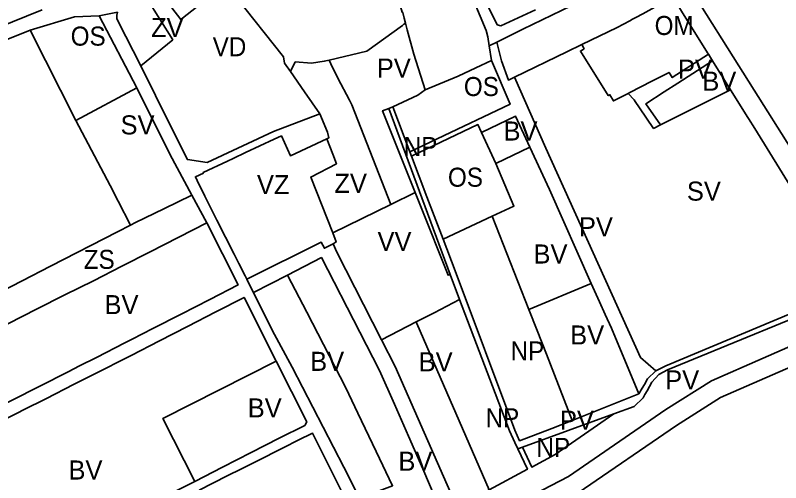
# Model space of a CAD drawing. Extents: x -650451 to -642268, y -1075216 to -1066610.
# Drawn here: x -648658 to -648056, y -1067753 to -1067385 of the extents above; entities that cross this region are included whole.
import ezdxf

# ---------------------------------------------------------------- set-up
doc = ezdxf.new("R2010")
doc.units = 0
doc.header["$LTSCALE"] = 6
doc.layers.add('1', color=7, linetype='Continuous', lineweight=35)
doc.layers.add('2', color=7, linetype='Continuous')
doc.layers.add('3', color=7, linetype='Continuous')

msp = doc.modelspace()

# ---------------------------------------------------------------- linework, layer by layer
at = {"layer": '1'}
for p, q in [((-648636.68, -1067380.92), (-648737.46, -1067421.52)), ((-648646.13, -1067396.91), (-648611.43, -1067386.42)), ((-648591.81, -1067385.65), (-648611.43, -1067386.42)), ((-648591.81, -1067385.65), (-648577.58, -1067382.79)), ((-648591.81, -1067385.65), (-648562.34, -1067442.47)), ((-648610.29, -1067468.28), (-648646.13, -1067396.91)), ((-648279.24, -1067406.38), (-648285.08, -1067409.24)), ((-648285.08, -1067409.24), (-648283.21, -1067420.88)), ((-648112.7, -1067416.03), (-648109.53, -1067421.13)), ((-648109.53, -1067421.13), (-648095.28, -1067444.06)), ((-648610.29, -1067468.28), (-648562.34, -1067442.47)), ((-648364.19, -1067458.619), (-648361, -1067457.36)), ((-648364.19, -1067458.619), (-648315.92, -1067589.37)), ((-648361, -1067457.36), (-648347.51, -1067492.87)), ((-648279.86, -1067502.11), (-648291.17, -1067477.57)), ((-648253.1, -1067489.23), (-648279.86, -1067502.11)), ((-648347.51, -1067492.87), (-648346.27, -1067496.14)), ((-648507.31, -1067548.84), (-648518.97, -1067527)), ((-648470.47, -1067603.64), (-648443.83, -1067589.92)), ((-648308.43, -1067609.15), (-648315.92, -1067589.37)), ((-648254.04, -1067616.96), (-648204.88, -1067596.54)), ((-648369.949, -1067640.851), (-648342.697, -1067626.806)), ((-648219.86, -1067704.42), (-648167.48, -1067683.45)), ((-648187.139, -1067699.179), (-648258.96, -1067725.37)), ((-648258.96, -1067725.37), (-648262.63, -1067726.71))]:
    msp.add_line(p, q, dxfattribs=at)
for points in [[(-648351.06, -1067391.62), (-648352.13, -1067387.54), (-648353.2, -1067383.1), (-648353.64, -1067382.91), (-648358.81, -1067364.78), (-648360.31, -1067359.89), (-648363.4, -1067349.23), (-648367.33, -1067340.58), (-648370.98, -1067331.37), (-648373.81, -1067324.53), (-648378.17, -1067313.98), (-648381.36, -1067306.74)], [(-647969.29, -1067609.79), (-647994.8, -1067572.37), (-648010.57, -1067549.31), (-648017.77, -1067537.87), (-648020.26, -1067533.91), (-648035.38, -1067509.89), (-648047.65, -1067490.38), (-648076.68, -1067444.23), (-648135.26, -1067351.13), (-648141.82, -1067342.88)], [(-648279.24, -1067406.38), (-648258.57, -1067396.29), (-648228.27, -1067381.48), (-648178.86, -1067357.46), (-648170.82, -1067354.57), (-648154.39, -1067349.06)], [(-648540.13, -1067358.49), (-648535.43, -1067364.69), (-648541.89, -1067369.86), (-648527.67, -1067388.73), (-648522.64, -1067384.7), (-648501.85, -1067367.87), (-648493.65, -1067361.24)], [(-648493.65, -1067361.24), (-648485.5, -1067371.06), (-648484.51, -1067370.58), (-648447.04, -1067418.08), (-648446.16, -1067422.92), (-648441.48, -1067429.63)], [(-648285.08, -1067409.24), (-648286.2, -1067402.2), (-648287.57, -1067397.28), (-648301.77, -1067363.07)], [(-648554.52, -1067371.95), (-648533.99, -1067404.51), (-648559.21, -1067425.12)], [(-648248.74, -1067380.92), (-648275.98, -1067393.72), (-648278.83, -1067392.79), (-648288.48, -1067372.88)], [(-648140.65, -1067371.06), (-648144.8, -1067373.45), (-648164.35, -1067384.16), (-648169.73, -1067387.11), (-648169.81, -1067386.98), (-648172.45, -1067388.4), (-648174.63, -1067389.58), (-648184.44, -1067394.86), (-648212.32, -1067408.39)], [(-648112.7, -1067416.03), (-648113.46, -1067414.8), (-648133.9, -1067381.99), (-648136.27, -1067378.19), (-648140.65, -1067371.06)], [(-648559.21, -1067425.12), (-648576.92, -1067390.11), (-648577.91, -1067387.81), (-648578.07, -1067385.28), (-648577.58, -1067382.79)], [(-648410.92, -1067420.63), (-648381.48, -1067413.68), (-648353.35, -1067393.29), (-648352.16, -1067392.42), (-648351.06, -1067391.62)], [(-648335.38, -1067444.07), (-648344.41, -1067416.04), (-648349.67, -1067396.88), (-648351.06, -1067391.62)], [(-648646.13, -1067396.91), (-648711.76, -1067423.39), (-648728.95, -1067430.33)], [(-648265.197, -1067434.03), (-648270.02, -1067436.37), (-648275.41, -1067421.3), (-648279.24, -1067406.38)], [(-648212.32, -1067408.39), (-648224.19, -1067414.14), (-648265.197, -1067434.03)], [(-648212.32, -1067408.39), (-648211.08, -1067410.6), (-648210.48, -1067411.68), (-648213.34, -1067413.46), (-648191.46, -1067448.59), (-648190.23, -1067447.83), (-648187.44, -1067452.8), (-648175.94, -1067446.89)], [(-648175.94, -1067446.89), (-648174.64, -1067446.22), (-648157.23, -1067437.28), (-648143.66, -1067430.3), (-648141.17, -1067434.4), (-648112.7, -1067416.03)], [(-648441.48, -1067429.63), (-648437.75, -1067421.99), (-648425, -1067423.05), (-648414.84, -1067421.56), (-648410.92, -1067420.63)], [(-648410.92, -1067420.63), (-648409.61, -1067423.44), (-648404.29, -1067434.9), (-648394.92, -1067452.23), (-648393.17, -1067455.88), (-648362.585, -1067534.204)], [(-648347.51, -1067492.87), (-648326.09, -1067482.7), (-648268.67, -1067455.43), (-648283.21, -1067420.88)], [(-648283.21, -1067420.88), (-648295.66, -1067426.76), (-648309.57, -1067433.34), (-648335.38, -1067444.07)], [(-648150.46, -1067471.66), (-648161.9, -1067454.92), (-648147.52, -1067445.69), (-648136.84, -1067438.83), (-648109.53, -1067421.13)], [(-648418.3, -1067462.86), (-648454.7, -1067476.79), (-648507.05, -1067501.14), (-648522.55, -1067498.89), (-648536.01, -1067471.76), (-648559.21, -1067425.12)], [(-648441.48, -1067429.63), (-648430.4, -1067445.51), (-648418.3, -1067462.86)], [(-648153.98, -1067665.43), (-648166.173, -1067654.853), (-648240.51, -1067489.9), (-648265.197, -1067434.03)], [(-648562.34, -1067442.47), (-648536.22, -1067494.67), (-648518.97, -1067527)], [(-648361, -1067457.36), (-648341.15, -1067448.14), (-648335.38, -1067444.07)], [(-648150.46, -1067471.66), (-648155.85, -1067474.35), (-648166.97, -1067458.18), (-648170.38, -1067453.23), (-648171.21, -1067452.01), (-648175.94, -1067446.89)], [(-648095.28, -1067444.06), (-648133.56, -1067463.2), (-648150.46, -1067471.66)], [(-648000.63, -1067599.14), (-648031.77, -1067546.6), (-648045.04, -1067525.15), (-648076.32, -1067474.6), (-648081.31, -1067466.54), (-648081.69, -1067465.92), (-648095.28, -1067444.06)], [(-648343.409, -1067524.81), (-648369.01, -1067460.52), (-648364.19, -1067458.619)], [(-648418.3, -1067462.86), (-648412.46, -1067477.42), (-648411.25, -1067481.73), (-648412.89, -1067482.55)], [(-648291.17, -1067477.57), (-648264.34, -1067464.83), (-648253.1, -1067489.23)], [(-648610.29, -1067468.28), (-648583.36, -1067519.43), (-648577.06, -1067531.62), (-648567.3, -1067550.48)], [(-648291.17, -1067477.57), (-648291.172, -1067477.571), (-648294.04, -1067471.35), (-648346.27, -1067496.14)], [(-648412.89, -1067482.55), (-648441.55, -1067495.94), (-648448.62, -1067480.25), (-648454.26, -1067482.89), (-648476.7, -1067493.38), (-648486.55, -1067498), (-648490.99, -1067500.08), (-648510.14, -1067509.04), (-648509.9, -1067509.58), (-648516.27, -1067512.46), (-648514.87, -1067515.48), (-648508.92, -1067527.65), (-648503.82, -1067537.85), (-648499.38, -1067546.74), (-648485.8, -1067573.49), (-648482.12, -1067580.73), (-648477.08, -1067590.47), (-648475.78, -1067593.11)], [(-648412.89, -1067482.55), (-648408.24, -1067494.59), (-648405.27, -1067502.27), (-648425.5, -1067512.73), (-648408.26, -1067556.58)], [(-648204.88, -1067596.54), (-648237.81, -1067522.42), (-648253.1, -1067489.23)], [(-648346.27, -1067496.14), (-648334.09, -1067528.2), (-648321.361, -1067561.69)], [(-648282.863, -1067543.596), (-648265.757, -1067535.555), (-648279.86, -1067502.11)], [(-648343.409, -1067524.81), (-648362.585, -1067534.204), (-648408.26, -1067556.58)], [(-648408.26, -1067556.58), (-648362.585, -1067534.205), (-648343.409, -1067524.81)], [(-648315.92, -1067589.37), (-648317.43, -1067590), (-648339.16, -1067535.48), (-648343.409, -1067524.81)], [(-648518.97, -1067527), (-648541.08, -1067537.74), (-648563.37, -1067548.58), (-648567.3, -1067550.48)], [(-648507.31, -1067548.84), (-648551.91, -1067571.47), (-648574.23, -1067582.89), (-648596.43, -1067594.35), (-648618.83, -1067605.54), (-648641.16, -1067616.88), (-648663.31, -1067628.15), (-648685.55, -1067639.55), (-648707.73, -1067650.94), (-648720.1, -1067657.12)], [(-648708.26, -1067712.07), (-648683.06, -1067699.88), (-648666.59, -1067691.63), (-648660.83, -1067688.75), (-648638.59, -1067677.44), (-648616.23, -1067666.06), (-648607.28, -1067661.48), (-648594.06, -1067654.71), (-648571.81, -1067643.31), (-648566.04, -1067640.39), (-648549.61, -1067632.06), (-648527.31, -1067620.61), (-648504.95, -1067609.19), (-648482.69, -1067597.72), (-648507.31, -1067548.84)], [(-648254.04, -1067616.96), (-648282.863, -1067543.596), (-648321.361, -1067561.69)], [(-648725.8, -1067632.36), (-648718.9, -1067628.79), (-648696.71, -1067617.33), (-648674.49, -1067605.85), (-648669.32, -1067603.18), (-648652.5, -1067594.5), (-648630.2, -1067582.97), (-648577.53, -1067555.77), (-648567.3, -1067550.48)], [(-648408.002, -1067565.219), (-648405.41, -1067563.84), (-648408.26, -1067556.58)], [(-648408.002, -1067565.219), (-648414.73, -1067568.8), (-648417.19, -1067564.02), (-648475.78, -1067593.11)], [(-648369.949, -1067640.851), (-648405.054, -1067571.837), (-648408.002, -1067565.219)], [(-648321.361, -1067561.69), (-648311.95, -1067586.45), (-648265.08, -1067712.06), (-648261.25, -1067720.39), (-648235.78, -1067710.79), (-648219.86, -1067704.42)], [(-648367.811, -1067802.994), (-648321.623, -1067778.399), (-648326, -1067769), (-648337.32, -1067742.59), (-648348.55, -1067716.71), (-648359.6, -1067691.58), (-648371.34, -1067665.08), (-648386.91, -1067634.83), (-648417.12, -1067576.17), (-648443.83, -1067589.92)], [(-648443.83, -1067589.92), (-648428.7, -1067619.24), (-648397.98, -1067678.79), (-648388.506, -1067698.645), (-648373.99, -1067728.95), (-648361.08, -1067755.88), (-648387.04, -1067765.67)], [(-648475.78, -1067593.11), (-648473.34, -1067598.06), (-648470.57, -1067603.69), (-648470.47, -1067603.64)], [(-648204.88, -1067596.54), (-648198.39, -1067610.97), (-648193.8, -1067621), (-648189.03, -1067631.71), (-648167.48, -1067683.45)], [(-648470.47, -1067603.64), (-648455.98, -1067633.3), (-648440.25, -1067662.32), (-648399.58, -1067741.31), (-648387.04, -1067765.67)], [(-648153.98, -1067665.43), (-648146.21, -1067661.3), (-648023.96, -1067610.13), (-648000.63, -1067599.14)], [(-648452.72, -1067657.62), (-648477.94, -1067607.47), (-648500.14, -1067618.94), (-648522.4, -1067630.35), (-648544.55, -1067641.82), (-648566.86, -1067653.13), (-648574.67, -1067657.12), (-648589.17, -1067664.52), (-648611.49, -1067675.9), (-648633.79, -1067687.24), (-648651.39, -1067696.1), (-648655.83, -1067698.33), (-648678.44, -1067709.73), (-648692.17, -1067716.68), (-648706.08, -1067723.56)], [(-648308.43, -1067609.15), (-648328.54, -1067619.51), (-648342.697, -1067626.806)], [(-648262.63, -1067726.71), (-648264.949, -1067721.79), (-648269.27, -1067712.6), (-648308.43, -1067609.15)], [(-647997.681, -1067604.11), (-648144.83, -1067664.48), (-648151.6, -1067668.12), (-648157.2, -1067674.32), (-648161, -1067680.96), (-648162.69, -1067684), (-648164.09, -1067686.51), (-648171.21, -1067693.37), (-648187.139, -1067699.179)], [(-647988.334, -1067619.747), (-648110.36, -1067673.133), (-648146.127, -1067695.8), (-648222.872, -1067748.412), (-648256.499, -1067766.091)], [(-648219.86, -1067704.42), (-648240.19, -1067652.12), (-648247.53, -1067633.53), (-648254.04, -1067616.96)], [(-648342.697, -1067626.806), (-648342.023, -1067628.096), (-648285.254, -1067759.009)], [(-647980.561, -1067632.719), (-648103.298, -1067686.416), (-648137.869, -1067708.325), (-648215.115, -1067761.28), (-648232.676, -1067770.513), (-648061.329, -1068158.649), (-647982.969, -1068116.575), (-647971.35, -1068144.48), (-647929.45, -1068244.16)], [(-648285.254, -1067759.009), (-648310.511, -1067772.476), (-648359.213, -1067661.956), (-648369.949, -1067640.851)], [(-648452.72, -1067657.62), (-648475.01, -1067668.94), (-648541.86, -1067702.86), (-648516.73, -1067752.57)], [(-648516.73, -1067752.57), (-648494.84, -1067741.06), (-648472.5, -1067729.76), (-648450.23, -1067718.32), (-648430.17, -1067708.33), (-648428.67, -1067705.52), (-648452.72, -1067657.62)], [(-648167.48, -1067683.45), (-648164.79, -1067678.96), (-648163.11, -1067676.17), (-648160.68, -1067671.55), (-648153.98, -1067665.43)], [(-648258.96, -1067725.37), (-648251.711, -1067741.124), (-648233.264, -1067731.288), (-648187.139, -1067699.179)], [(-648611.61, -1067932.63), (-648547.09, -1067899.87), (-648530.81, -1067891.61), (-648508.22, -1067880.38), (-648486.09, -1067868.98), (-648441.47, -1067846.37), (-648419.44, -1067835.3), (-648397.04, -1067823.85), (-648374.84, -1067812.43), (-648399.64, -1067763.26), (-648424.14, -1067714.34), (-648435.34, -1067720.01), (-648446.58, -1067725.71), (-648468.97, -1067736.91), (-648480.06, -1067742.47), (-648491.14, -1067748.02), (-648513.23, -1067759.38)], [(-648262.63, -1067726.71), (-648262.632, -1067726.711), (-648255.016, -1067742.886), (-648285.254, -1067759.009)], [(-648516.73, -1067752.57), (-648539.31, -1067763.71), (-648561.71, -1067774.93), (-648584.13, -1067786.06), (-648606.09, -1067797.19), (-648628.99, -1067808.91), (-648686.7, -1067838.45), (-648692.08, -1067836.26), (-648699.59, -1067840.06), (-648699.593, -1067840.046)]]:
    msp.add_lwpolyline(points, dxfattribs=at)

# ---------------------------------------------------------------- texts
at = {"layer": '2', "width": 0.95}
for s, p in [('OM', (-648155.01, -1067400.84)), ('OS', (-648614.34, -1067409.21)), ('VD', (-648502.65, -1067417.575)), ('NP', (-648352.404, -1067496.227)), ('ZS', (-648604.07, -1067585.027))]:
    msp.add_text(s, height=15, dxfattribs=at).set_placement(p)
at = {"layer": '2'}
for s, p in [('ZV', (-648551.13, -1067402.43)), ('PV', (-648136.665, -1067435.25)), ('BV', (-648117.504, -1067444.663)), ('SV', (-648575.11, -1067479.12)), ('BV', (-648273.878, -1067483.941)), ('VZ', (-648467.82, -1067526.143)), ('BV', (-648587.739, -1067620.676)), ('BV', (-648221.445, -1067644.577)), ('BV', (-648425.992, -1067665.328)), ('PV', (-648229.483, -1067711.666)), ('BV', (-648616.087, -1067750.927))]:
    msp.add_text(s, height=15, dxfattribs=at).set_placement(p)
at = {"layer": '3'}
for s, p in [('PV', (-648373.558, -1067434.373)), ('ZV', (-648406.932, -1067525.168)), ('SV', (-648129.658, -1067531.285)), ('PV', (-648214.576, -1067559.386)), ('VV', (-648372.99, -1067570.89)), ('BV', (-648250.298, -1067580.794)), ('BV', (-648340.636, -1067665.724)), ('PV', (-648146.741, -1067679.96)), ('BV', (-648475.079, -1067702)), ('BV', (-648356.57, -1067743.97))]:
    msp.add_text(s, height=15, dxfattribs=at).set_placement(p)
at = {"layer": '3', "width": 0.95}
for s, p in [('OS', (-648305.07, -1067448.914)), ('OS', (-648317.59, -1067520.332)), ('NP', (-648268.32, -1067657.16)), ('NP', (-648287.964, -1067709.791)), ('NP', (-648247.934, -1067733.142))]:
    msp.add_text(s, height=15, dxfattribs=at).set_placement(p)

doc.saveas('drawing.dxf')
